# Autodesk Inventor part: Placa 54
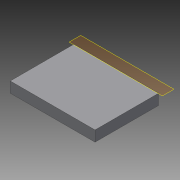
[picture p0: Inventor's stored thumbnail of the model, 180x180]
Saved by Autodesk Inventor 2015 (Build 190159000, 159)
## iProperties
Created: 2015-04
Part Number: Placa 54
Material: Generic
Document SubType Name: Modeling
Designer: suporte
Density: 1 g/cm^3
Appearance: Default
Author: suporte
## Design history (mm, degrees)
workplane "Work Plane1"
sketch "Sketch1"
  geometry: L1 (-100, 0)-(0, 0) reference; L2 (-100, 0)-(-100, -12.5) reference; L3 (0, -12.5)-(-100, -12.5) reference; L4 (0, 0)-(0, -12.5) reference; L5 (0, -12.5)-(-100, -12.5); L6 (-100, -12.5)-(-100, -87.5); L7 (-100, -87.5)-(0, -87.5); L8 (0, -87.5)-(0, -12.5)
  constraints: 8 end point, 2 parallel, 1 horizontal, 1 perpendicular
  dimensions: "d0" = 100 distance of L7.end L6.end; "d1" = 75 distance of L6.end L5.end
extrude "Extrusion1" new body sketch "Sketch1" distance "d2" = 12.5; taper "d3" = 0 deg
body "Solid1"
node "Reference1"
